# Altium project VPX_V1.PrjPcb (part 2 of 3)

## Sheet 28V to 12V drivers.SchDoc
size 431 x 279 mm; Date: Not shown in title block; ApprovedBy: Not shown in title block; CheckedBy: Not shown in title block; Author: Not shown in title block; CompanyName: Not shown in title block; Engineer: Not shown in title block; Organization: Not shown in title block; Address1: Not shown in title block; Address2: Not shown in title block; Address3: Not shown in title block; Address4: Not shown in title block; DocumentNumber: 2; Revision: Use project parameter SCH_Rev; SheetNumber: 4; SheetTotal: 8; PageSetup: Record=PageOptions¦CenterHorizontal=True¦CenterVertical=True¦PrintScale=1.00¦XCorrection=1.00¦YCorrection=1.00¦PrintKind=0¦BorderSize=5000000¦LeftOffset=0¦BottomOffset=0¦Orientation=2¦PaperLength=1000¦PaperWidth=1000¦Scale=100¦PaperSource=15¦PrintQuality=600¦MediaType=1¦DitherType=10¦PaperKind=Letter¦PrintScaleMode=1
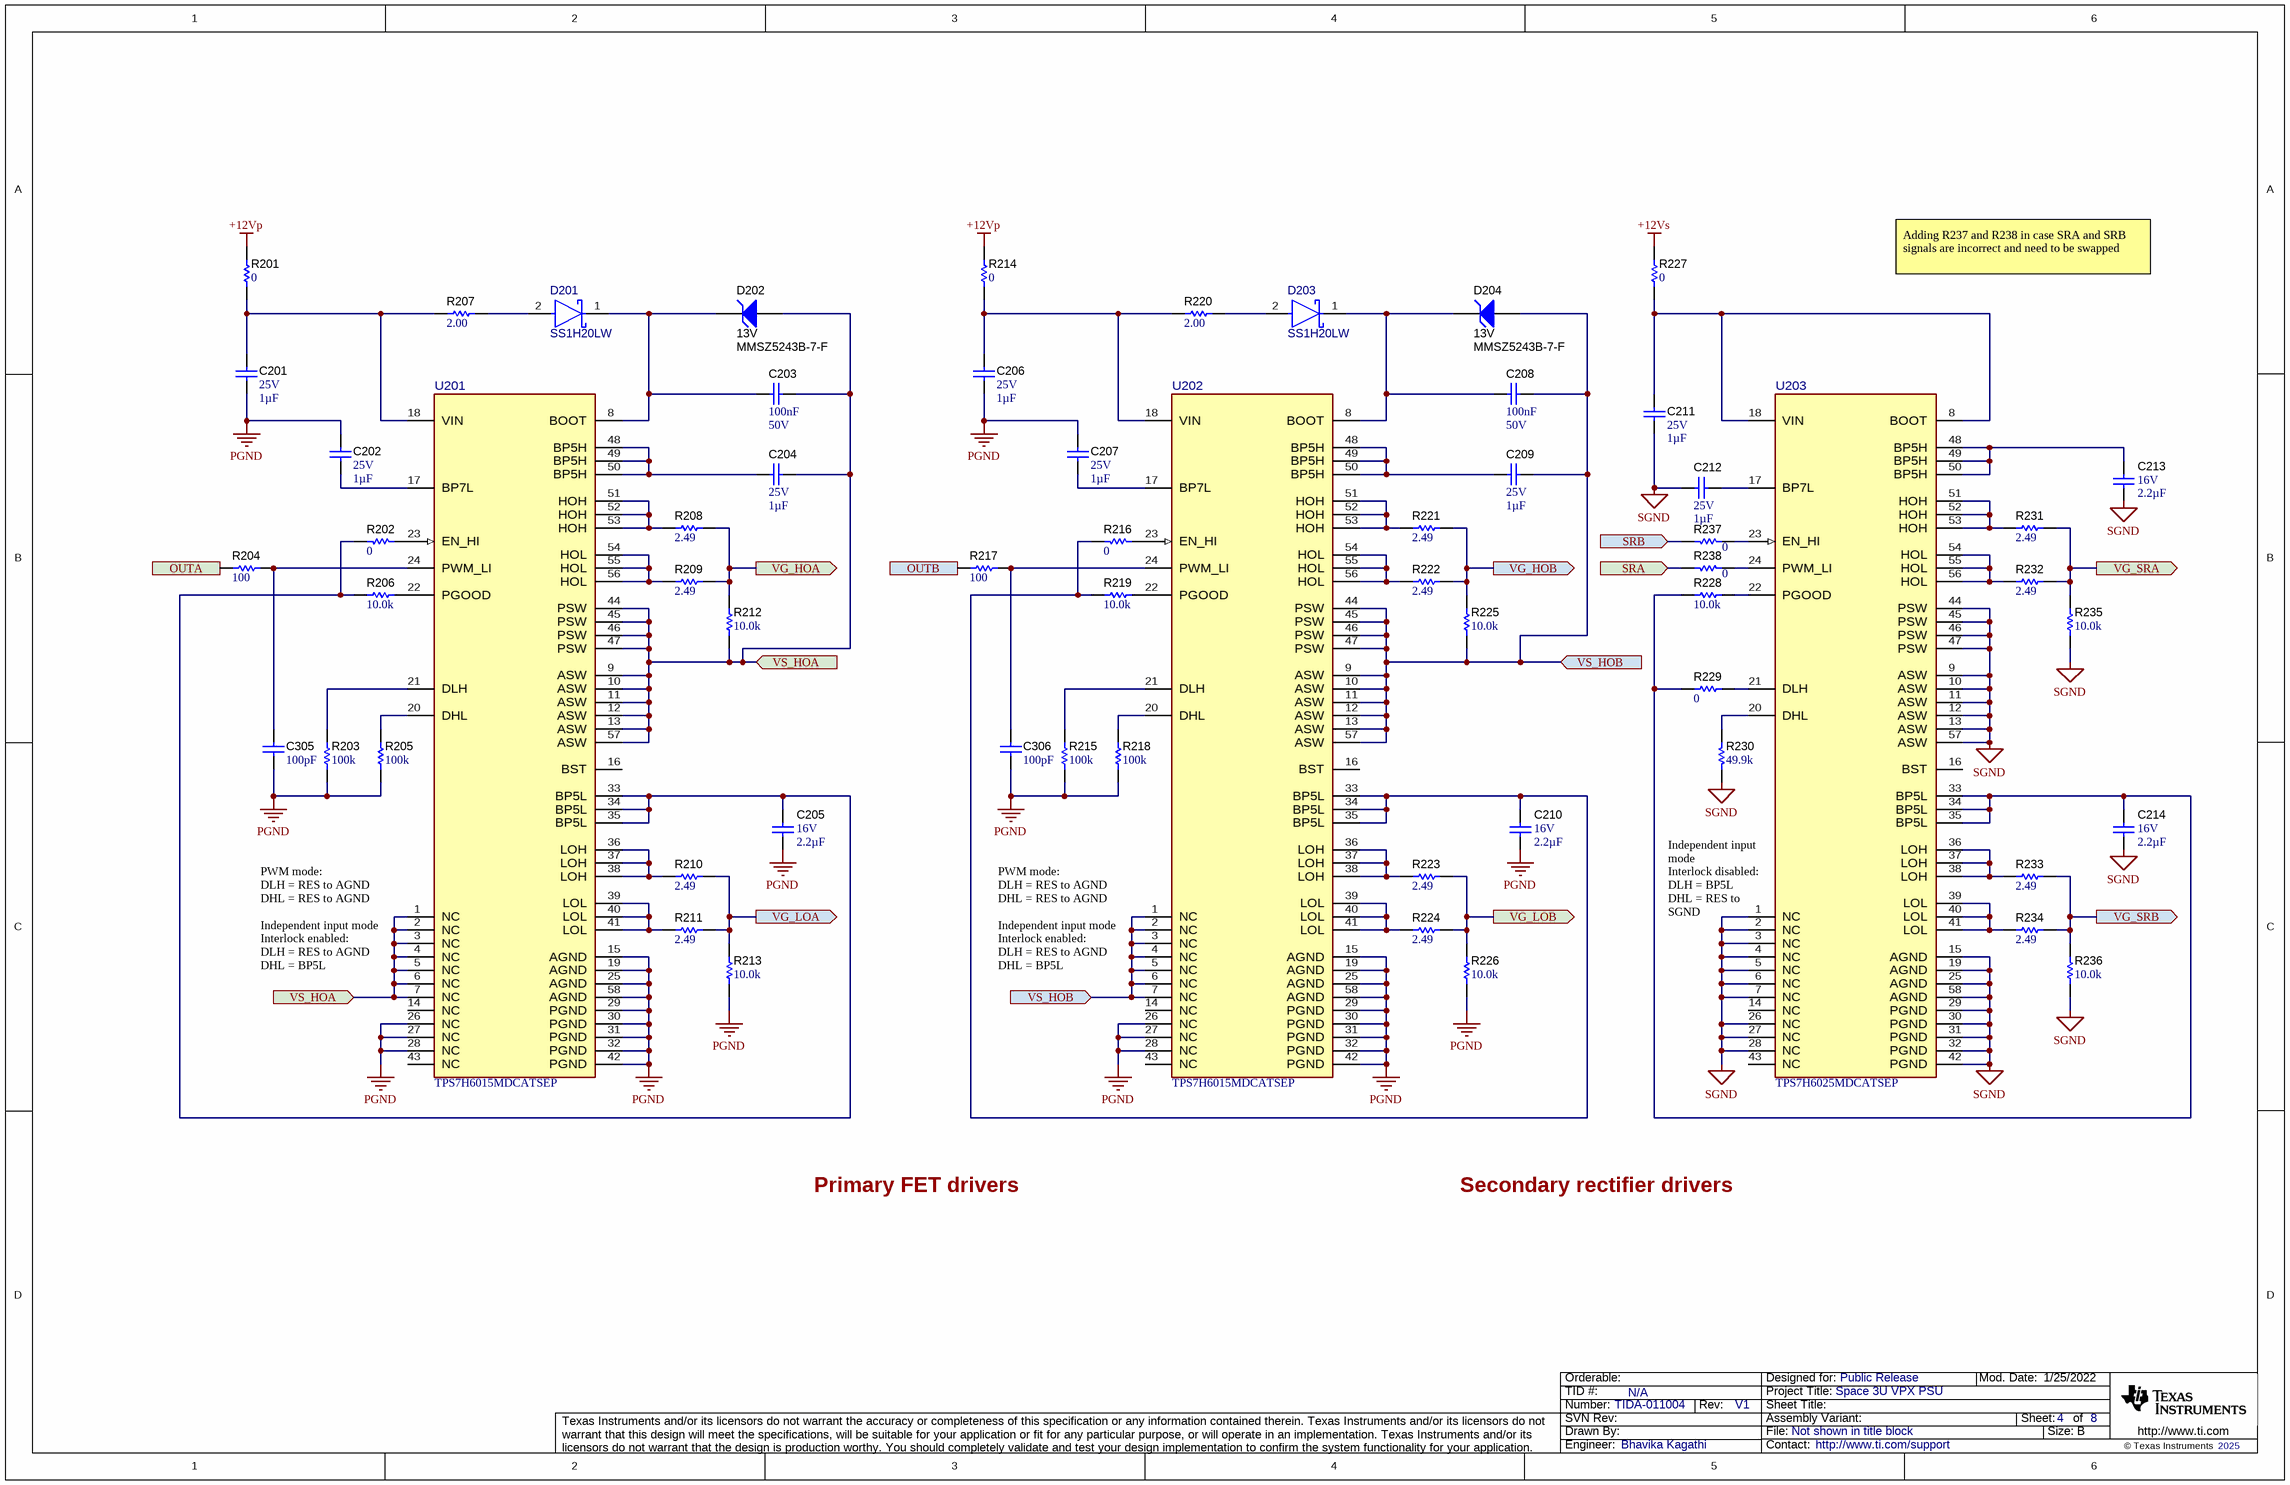
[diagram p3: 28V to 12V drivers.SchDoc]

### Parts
C201  VDC_V: 25V  Cap_F: 1µF  [0603]  (hidden comment: C0603C105K3RACTU)
C202  VDC_V: 25V  Cap_F: 1µF  [0603]  (hidden comment: C0603C105K3RACTU)
C203  Cap_F: 100nF  VDC_V: 50V  [0603_HV]  (hidden comment: C0603C104K5RACAUTO)
C204  VDC_V: 25V  Cap_F: 1µF  [0603]  (hidden comment: C0603C105K3RACTU)
C205  VDC_V: 16V  Cap_F: 2.2µF  [0603_HV]  (hidden comment: GRM188Z71C225KE43)
C206  VDC_V: 25V  Cap_F: 1µF  [0603]  (hidden comment: C0603C105K3RACTU)
C207  VDC_V: 25V  Cap_F: 1µF  [0603]  (hidden comment: C0603C105K3RACTU)
C208  Cap_F: 100nF  VDC_V: 50V  [0603_HV]  (hidden comment: C0603C104K5RACAUTO)
C209  VDC_V: 25V  Cap_F: 1µF  [0603]  (hidden comment: C0603C105K3RACTU)
C210  VDC_V: 16V  Cap_F: 2.2µF  [0603_HV]  (hidden comment: GRM188Z71C225KE43)
C211  VDC_V: 25V  Cap_F: 1µF  [0603]  (hidden comment: C0603C105K3RACTU)
C212  VDC_V: 25V  Cap_F: 1µF  [0603]  (hidden comment: C0603C105K3RACTU)
C213  VDC_V: 16V  Cap_F: 2.2µF  [0603_HV]  (hidden comment: GRM188Z71C225KE43)
C214  VDC_V: 16V  Cap_F: 2.2µF  [0603_HV]  (hidden comment: GRM188Z71C225KE43)
C305  ValueDisplayed: 100pF  [0603_HV]  (hidden comment: GRM1885C1H101JA01D)
C306  ValueDisplayed: 100pF  [0603_HV]  (hidden comment: GRM1885C1H101JA01D)
D201  SS1H20LW  [FP-SS1H20LW_SOD-123W-MFG]
D202  MMSZ5243B-7-F  value 13V  [SOD-123]
D203  SS1H20LW  [FP-SS1H20LW_SOD-123W-MFG]
D204  MMSZ5243B-7-F  value 13V  [SOD-123]
R201  ValueDisplayed: 0  [0603_HV]  (hidden comment: CRCW06030000Z0EA)
R202  ValueDisplayed: 0  [0603_HV]  (hidden comment: CRCW06030000Z0EA)
R203  ValueDisplayed: 100k  [0603_HV]  (hidden comment: CRCW0603100KFKEA)
R204  ValueDisplayed: 100  [0603_HV]  (hidden comment: CRCW0603100RJNEA)
R205  ValueDisplayed: 100k  [0603_HV]  (hidden comment: CRCW0603100KFKEA)
R206  ValueDisplayed: 10.0k  [0603_HV]  (hidden comment: CRCW060310K0FKEA)
R207  ValueDisplayed: 2.00  [0603_HV]  (hidden comment: MCT06030C2008FP500)
R208  ValueDisplayed: 2.49  [0603_HV]  (hidden comment: CRCW06032R49FKEA)
R209  ValueDisplayed: 2.49  [0603_HV]  (hidden comment: CRCW06032R49FKEA)
R210  ValueDisplayed: 2.49  [0603_HV]  (hidden comment: CRCW06032R49FKEA)
R211  ValueDisplayed: 2.49  [0603_HV]  (hidden comment: CRCW06032R49FKEA)
R212  ValueDisplayed: 10.0k  [0603_HV]  (hidden comment: CRCW060310K0FKEA)
R213  ValueDisplayed: 10.0k  [0603_HV]  (hidden comment: CRCW060310K0FKEA)
R214  ValueDisplayed: 0  [0603_HV]  (hidden comment: CRCW06030000Z0EA)
R215  ValueDisplayed: 100k  [0603_HV]  (hidden comment: CRCW0603100KFKEA)
R216  ValueDisplayed: 0  [0603_HV]  (hidden comment: CRCW06030000Z0EA)
R217  ValueDisplayed: 100  [0603_HV]  (hidden comment: CRCW0603100RJNEA)
R218  ValueDisplayed: 100k  [0603_HV]  (hidden comment: CRCW0603100KFKEA)
R219  ValueDisplayed: 10.0k  [0603_HV]  (hidden comment: CRCW060310K0FKEA)
R220  ValueDisplayed: 2.00  [0603_HV]  (hidden comment: MCT06030C2008FP500)
R221  ValueDisplayed: 2.49  [0603_HV]  (hidden comment: CRCW06032R49FKEA)
R222  ValueDisplayed: 2.49  [0603_HV]  (hidden comment: CRCW06032R49FKEA)
R223  ValueDisplayed: 2.49  [0603_HV]  (hidden comment: CRCW06032R49FKEA)
R224  ValueDisplayed: 2.49  [0603_HV]  (hidden comment: CRCW06032R49FKEA)
R225  ValueDisplayed: 10.0k  [0603_HV]  (hidden comment: CRCW060310K0FKEA)
R226  ValueDisplayed: 10.0k  [0603_HV]  (hidden comment: CRCW060310K0FKEA)
R227  ValueDisplayed: 0  [0603_HV]  (hidden comment: CRCW06030000Z0EA)
R228  ValueDisplayed: 10.0k  [0603_HV]  (hidden comment: CRCW060310K0FKEA)
R229  ValueDisplayed: 0  [0603_HV]  (hidden comment: CRCW06030000Z0EA)
R230  ValueDisplayed: 49.9k  [0603_HV]  (hidden comment: CRCW060349K9FKEA)
R231  ValueDisplayed: 2.49  [0603_HV]  (hidden comment: CRCW06032R49FKEA)
R232  ValueDisplayed: 2.49  [0603_HV]  (hidden comment: CRCW06032R49FKEA)
R233  ValueDisplayed: 2.49  [0603_HV]  (hidden comment: CRCW06032R49FKEA)
R234  ValueDisplayed: 2.49  [0603_HV]  (hidden comment: CRCW06032R49FKEA)
R235  ValueDisplayed: 10.0k  [0603_HV]  (hidden comment: CRCW060310K0FKEA)
R236  ValueDisplayed: 10.0k  [0603_HV]  (hidden comment: CRCW060310K0FKEA)
R237  ValueDisplayed: 0  [0603_HV]  (hidden comment: CRCW06030000Z0EA)
R238  ValueDisplayed: 0  [0603_HV]  (hidden comment: CRCW06030000Z0EA)
U201  PartNumber: TPS7H6015MDCATSEP  [DCA0056M-MFG]  (hidden comment: TPS7H6005/EM)
U202  PartNumber: TPS7H6015MDCATSEP  [DCA0056M-MFG]  (hidden comment: TPS7H6005/EM)
U203  PartNumber: TPS7H6025MDCATSEP  [DCA0056M-MFG]  (hidden comment: TPS7H6005/EM)

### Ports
OUTA (in), OUTB (in), SRA (in), SRB (in), VG_HOA (out), VG_HOB (out), VG_LOA (out), VG_LOB (out), VG_SRA (out), VG_SRB (out), VS_HOA (in), VS_HOB (in)

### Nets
+12Vp: R201.1 R214.1
+12Vs: R227.1
PGND: C201.2 C202.1 C205.1 C206.2 C207.1 C210.1 C305.1 C306.1 R203.1 R205.1 R213.2 R215.1 R218.1 R226.2 U201.15(AGND) U201.19(AGND) U201.25(AGND) U201.26(NC) U201.27(NC) U201.28(NC) U201.29(PGND) U201.30(PGND) U201.31(PGND) U201.32(PGND) U201.42(PGND) U201.58(AGND) U202.15(AGND) U202.19(AGND) U202.25(AGND) U202.26(NC) U202.27(NC) U202.28(NC) U202.29(PGND) U202.30(PGND) U202.31(PGND) U202.32(PGND) U202.42(PGND) U202.58(AGND)
SGND: C211.2 C212.1 C213.1 C214.1 R230.2 R235.2 R236.2 U203.1(NC) U203.2(NC) U203.3(NC) U203.4(NC) U203.5(NC) U203.6(NC) U203.7(NC) U203.9(ASW) U203.10(ASW) U203.11(ASW) U203.12(ASW) U203.13(ASW) U203.15(AGND) U203.19(AGND) U203.25(AGND) U203.26(NC) U203.27(NC) U203.28(NC) U203.29(PGND) U203.30(PGND) U203.31(PGND) U203.32(PGND) U203.42(PGND) U203.44(PSW) U203.45(PSW) U203.46(PSW) U203.47(PSW) U203.57(ASW) U203.58(AGND)
OUTA: R204.2 ; port OUTA
OUTB: R217.2 ; port OUTB
SRA: R238.1 ; port SRA
SRB: R237.1 ; port SRB
VG_HOA: R208.1 R209.1 R212.1 ; port VG_HOA
VG_HOB: R221.1 R222.1 R225.1 ; port VG_HOB
VG_LOA: R210.1 R211.1 R213.1 ; port VG_LOA
VG_LOB: R223.1 R224.1 R226.1 ; port VG_LOB
VG_SRA: R231.1 R232.1 R235.1 ; port VG_SRA
VG_SRB: R233.1 R234.1 R236.1 ; port VG_SRB
VS_HOA: C203.2 C204.2 D202.2(A) R212.2 U201.1(NC) U201.2(NC) U201.3(NC) U201.4(NC) U201.5(NC) U201.6(NC) U201.7(NC) U201.9(ASW) U201.10(ASW) U201.11(ASW) U201.12(ASW) U201.13(ASW) U201.44(PSW) U201.45(PSW) U201.46(PSW) U201.47(PSW) U201.57(ASW) ; port VS_HOA
VS_HOB: C208.2 C209.2 D204.2(A) R225.2 U202.1(NC) U202.2(NC) U202.3(NC) U202.4(NC) U202.5(NC) U202.6(NC) U202.7(NC) U202.9(ASW) U202.10(ASW) U202.11(ASW) U202.12(ASW) U202.13(ASW) U202.44(PSW) U202.45(PSW) U202.46(PSW) U202.47(PSW) U202.57(ASW) ; port VS_HOB
NetC201_1: C201.1 R201.2 R207.1 U201.18(VIN)
NetC202_2: C202.2 U201.17(BP7L)
NetC203_1: C203.1 D201.1(CATHODE) D202.1(K) U201.8(BOOT)
NetC204_1: C204.1 U201.48(BP5H) U201.49(BP5H) U201.50(BP5H)
NetC205_2: C205.2 R202.1 R206.2 U201.33(BP5L) U201.34(BP5L) U201.35(BP5L)
NetC206_1: C206.1 R214.2 R220.1 U202.18(VIN)
NetC207_2: C207.2 U202.17(BP7L)
NetC208_1: C208.1 D203.1(CATHODE) D204.1(K) U202.8(BOOT)
NetC209_1: C209.1 U202.48(BP5H) U202.49(BP5H) U202.50(BP5H)
NetC210_2: C210.2 R216.1 R219.2 U202.33(BP5L) U202.34(BP5L) U202.35(BP5L)
NetC211_1: C211.1 R227.2 U203.8(BOOT) U203.18(VIN)
NetC212_2: C212.2 U203.17(BP7L)
NetC213_2: C213.2 U203.48(BP5H) U203.49(BP5H) U203.50(BP5H)
NetC214_2: C214.2 R228.2 R229.1 U203.33(BP5L) U203.34(BP5L) U203.35(BP5L)
NetC305_2: C305.2 R204.1 U201.24(PWM_LI)
NetC306_2: C306.2 R217.1 U202.24(PWM_LI)
NetD201_2: D201.2(ANODE) R207.2
NetD203_2: D203.2(ANODE) R220.2
NetR202_2: R202.2 U201.23(EN_HI)
NetR203_2: R203.2 U201.21(DLH)
NetR205_2: R205.2 U201.20(DHL)
NetR206_1: R206.1 U201.22(PGOOD)
NetR208_2: R208.2 U201.51(HOH) U201.52(HOH) U201.53(HOH)
NetR209_2: R209.2 U201.54(HOL) U201.55(HOL) U201.56(HOL)
NetR210_2: R210.2 U201.36(LOH) U201.37(LOH) U201.38(LOH)
NetR211_2: R211.2 U201.39(LOL) U201.40(LOL) U201.41(LOL)
NetR215_2: R215.2 U202.21(DLH)
NetR216_2: R216.2 U202.23(EN_HI)
NetR218_2: R218.2 U202.20(DHL)
NetR219_1: R219.1 U202.22(PGOOD)
NetR221_2: R221.2 U202.51(HOH) U202.52(HOH) U202.53(HOH)
NetR222_2: R222.2 U202.54(HOL) U202.55(HOL) U202.56(HOL)
NetR223_2: R223.2 U202.36(LOH) U202.37(LOH) U202.38(LOH)
NetR224_2: R224.2 U202.39(LOL) U202.40(LOL) U202.41(LOL)
NetR228_1: R228.1 U203.22(PGOOD)
NetR229_2: R229.2 U203.21(DLH)
NetR230_1: R230.1 U203.20(DHL)
NetR231_2: R231.2 U203.51(HOH) U203.52(HOH) U203.53(HOH)
NetR232_2: R232.2 U203.54(HOL) U203.55(HOL) U203.56(HOL)
NetR233_2: R233.2 U203.36(LOH) U203.37(LOH) U203.38(LOH)
NetR234_2: R234.2 U203.39(LOL) U203.40(LOL) U203.41(LOL)
NetR237_2: R237.2 U203.23(EN_HI)
NetR238_2: R238.2 U203.24(PWM_LI)

Not connected (* = marked no-connect by the designer): U201 14(NC) 16(BST) 43(NC); U202 14(NC) 16(BST) 43(NC); U203 14(NC) 16(BST) 43(NC)

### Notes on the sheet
- Adding R237 and R238 in case SRA and SRB signals are incorrect and need to be swapped
- PWM mode:
  DLH = RES to AGND
  DHL = RES to AGND
- Independent input mode
  Interlock enabled:
  DLH = RES to AGND
  DHL = BP5L
- (near U203) Independent input mode
  Interlock disabled:
  DLH = BP5L
  DHL = RES to SGND
- Primary FET drivers
- Secondary rectifier drivers

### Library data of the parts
C201 C202 C204 C206 C207 C209 C211 C212 = CMP-0006867-4: CAP, CERM, 1 uF, 25 V, +/- 10%, X7R, 0603; Manufacturer: Kemet; AEC Category: Q200; Value: 1uF; SizeX_mm: 1.6; U/M: EA; Value1: Unknown; SizeAreaWB_mm2: 4.68; SizeY_mm: 0.8; TaMin_C: -55°C; SizeZ_mm: 1; Polarized: N; TaMax_C: 125°C; SizeArea_mm2: 1.28
C203 C208 = CMP-0079602-1: CAP, CERM, 0.1 µF, 50 V,+/- 10%, X7R, AEC-Q200 Grade 1, 0603; Manufacturer: Kemet; TaMin_C: -55°C; Polarized: N; SizeAreaWB_mm2: 4.68; U/M: EA; Value: 0.1uF; TaMax_C: 125°C; SizeZ_mm: 1; SizeX_mm: 1.6; SizeY_mm: 0.8; Cap_Case: 0603; SizeArea_mm2: 1.28; AEC Qualified: Y; AEC Category: Q200; ValueDisplayed: 0.1µF
C205 C210 C213 C214 = CMP-0007499-4: CAP, CERM, 2.2 uF, 16 V, +/- 10%, X7R, 0603; Manufacturer: MuRata; TaMin_C: -55°C; Polarized: N; SizeAreaWB_mm2: 4.68; Value1: Unknown; U/M: EA; Value: 2.2uF; TaMax_C: 125°C; SizeZ_mm: 1; SizeX_mm: 1.6; SizeY_mm: 0.8; Cap_Case: 0603; SizeArea_mm2: 1.28; AEC Category: Q200
C305 C306 = CMP-0007171-4: CAP, CERM, 100 pF, 50 V, +/- 5%, C0G/NP0, 0603; Manufacturer: MuRata; TaMin_C: -55°C; Polarized: N; SizeAreaWB_mm2: 4.68; Value1: Unknown; U/M: EA; Value: 100pF; TaMax_C: 125°C; SizeZ_mm: 1; SizeX_mm: 1.6; SizeY_mm: 0.8; Cap_Case: 0603; Value2: 50V; SizeArea_mm2: 1.28; AEC Category: Q200
D201 D203 = CMP-0095320-1: Diode Schottky 200 V 1A Surface Mount SOD-123W; Manufacturer: Taiwan Semiconductor; Max Surge Forward Current: 30A; SizeZ_mm: 1.02mm; AEC Qualified: No; Vf_V: 200V; TJmax_C: 175°C; Peak Reverse Current: 0.1mA; Standoff Height: 0mm
D202 D204 = CMP-0005752-4: Diode, Zener, 13 V, 500 mW, SOD-123; Manufacturer: Diodes Inc.; Value1: 0.5W; SizeAreaWB_mm2: 13.095; RJA_CperW: 350; AEC Category: Q101; SizeZ_mm: 1.35; SizeX_mm: 3.85; Power_W: 500mW; SizeArea_mm2: 6.545; SizeY_mm: 1.7
R201 R202 R214 R216 R227 R229 R237 R238 = CMP-0025697-4: RES, 0, 5%, 0.1 W, AEC-Q200 Grade 0, 0603; Manufacturer: Vishay-Dale; Power_W: 100mW; TempCo: 200 ppm/C; Value_Code: 0000; Value: 0; EIA_Code: E24; SizeX_mm: 1.6; SizeY_mm: 0.8; SizeZ_mm: 1; Value2: 0.1W; SizeArea_mm2: 1.28; AEC Qualified: Y; VDC_V: 75V; AEC Category: Q200
R203 R205 R215 R218 = CMP-0021990-4: RES, 100 k, 1%, 0.1 W, AEC-Q200 Grade 0, 0603; Manufacturer: Vishay-Dale; Power_W: 100mW; TempCo: 100 ppm/C; Value: 100k; EIA_Code: E96; SizeX_mm: 1.6; SizeY_mm: 0.8; SizeZ_mm: 1; Value2: 0.1W; SizeArea_mm2: 1.28; AEC Qualified: Y; VDC_V: 75V; AEC Category: Q200; AEC Grade: 0
R204 R217 = CMP-0025700-4: RES, 100, 5%, 0.1 W, AEC-Q200 Grade 0, 0603; Manufacturer: Vishay-Dale; Power_W: 100mW; TempCo: 200 ppm/C; Value_Code: 100R; Value: 100; EIA_Code: E24; SizeX_mm: 1.6; SizeY_mm: 0.8; SizeZ_mm: 1; Value2: 0.1W; SizeArea_mm2: 1.28; AEC Qualified: Y; VDC_V: 75V; AEC Category: Q200; AEC Grade: 0
R206 R212 R213 R219 R225 R226 R228 R235 R236 = CMP-0021998-4: RES, 10.0 k, 1%, 0.1 W, AEC-Q200 Grade 0, 0603; Manufacturer: Vishay-Dale; Power_W: 100mW; TempCo: 100 ppm/C; Value_Code: 10k0; Value: 10.0k; EIA_Code: E96; Res_ohm: 10k; SizeX_mm: 1.6; SizeY_mm: 0.8; SizeZ_mm: 1; Value2: 0.1W; SizeArea_mm2: 1.28; AEC Qualified: Y; VDC_V: 75V; AEC Category: Q200; AEC Grade: 0
R207 R220 = CMP-0022732-2: RES, 2.00, 1%, 0.125 W, 0603; Manufacturer: Vishay/Beyschlag; Power_W: 125mW; TempCo: 50 ppm/C; Value_Code: 2R00; U/M: EA; Value: 2.00; EIA_Code: E96; Res_ohm: 2; SizeX_mm: 1.6; SizeY_mm: 0.8; Value2: 0.125W; SizeArea_mm2: 1.28; AEC Qualified: N; AEC Category: Q200; SizeZ_mm: 1
R208-R211 R221-R224 R231-R234 = CMP-0022311-4: RES, 2.49, 1%, 0.1 W, AEC-Q200 Grade 0, 0603; Manufacturer: Vishay-Dale; Power_W: 100mW; TempCo: 100 ppm/C; Value_Code: 2R49; Value: 2.49; EIA_Code: E96; SizeX_mm: 1.6; SizeY_mm: 0.8; SizeZ_mm: 1; Value2: 0.1W; SizeArea_mm2: 1.28; AEC Qualified: Y; VDC_V: 75V; AEC Category: Q200; AEC Grade: 0
R230 = CMP-0022447-4: RES, 49.9 k, 1%, 0.1 W, AEC-Q200 Grade 0, 0603; Manufacturer: Vishay-Dale; Power_W: 100mW; TempCo: 100 ppm/C; Value_Code: 49k9; Value: 49.9k; EIA_Code: E96; SizeX_mm: 1.6; SizeY_mm: 0.8; SizeZ_mm: 1; Value2: 0.1W; SizeArea_mm2: 1.28; AEC Qualified: Y; VDC_V: 75V; AEC Category: Q200; AEC Grade: 0
U201-U203 = CMP-0120202-4: Manufacturer: Texas Instruments; SizeZ_mm: 1.2mm; Standoff Height: 0.05mm; AEC Category: Q200; CompType: IC

## Sheet 12V to 5V.SchDoc
size 558 x 431 mm; Date: Not shown in title block; ApprovedBy: Not shown in title block; CheckedBy: Not shown in title block; Author: Not shown in title block; CompanyName: Not shown in title block; Engineer: Not shown in title block; Organization: Not shown in title block; Address1: Not shown in title block; Address2: Not shown in title block; Address3: Not shown in title block; Address4: Not shown in title block; DocumentNumber: 1; Revision: Use project parameter SCH_Rev; SheetNumber: 5; SheetTotal: 8; PageSetup: Record=PageOptions¦CenterHorizontal=True¦CenterVertical=True¦PrintScale=1.00¦XCorrection=1.00¦YCorrection=1.00¦PrintKind=0¦BorderSize=5000000¦LeftOffset=0¦BottomOffset=0¦Orientation=2¦PaperLength=1000¦PaperWidth=1000¦Scale=100¦PaperSource=15¦PrintQuality=600¦MediaType=1¦DitherType=10¦PaperKind=Letter¦PrintScaleMode=1
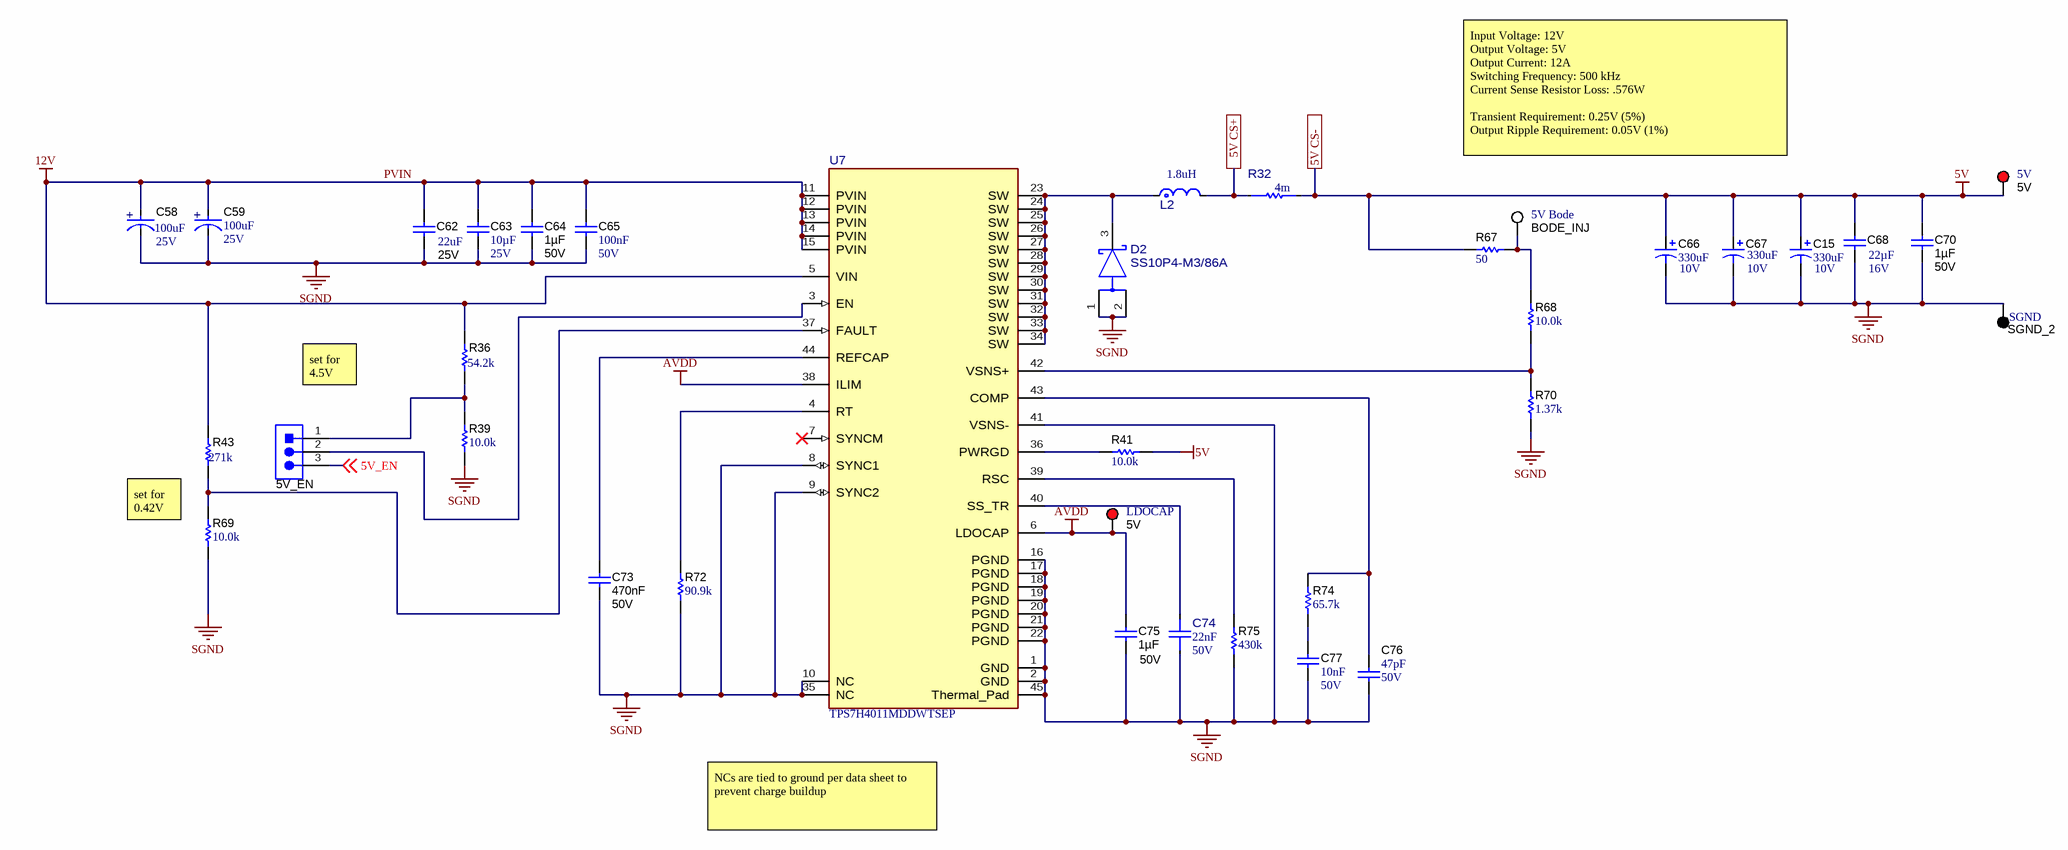
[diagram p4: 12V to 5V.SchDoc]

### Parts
5V  5V  [Keystone5010]
5V_Bode  BODE_INJ  [Keystone5012]
5V_EN  PTT-103-01-L-S  [Samtec_PTT-103-01-x-S]  (value not drawn)
C15  ValueDisplayed: 330uF  VDC_V: 10V  [7343-43]  (hidden comment: T530X337M010ATE006)
C58  ValueDisplayed: 100uF  VDC_V: 25V  [FP-T521D107M025ATE040_2917-MFG]  (hidden comment: T521D107M025ATE040)
C59  ValueDisplayed: 100uF  VDC_V: 25V  [FP-T521D107M025ATE040_2917-MFG]  (hidden comment: T521D107M025ATE040)
C62  Value2: 25V  ValueDisplayed: 22uF  [0805_HV]  (hidden comment: GRM21BR61E226ME44L)
C63  Cap_F: 10µF  VDC_V: 25V  [0805_HV]  (hidden comment: GRM21BZ71E106KE15L)
C64  Cap_F: 1µF  VDC_V: 50V  [0805]  (hidden comment: CL21B105KBFNFNE)
C65  Cap_F: 100nF  VDC_V: 50V  [0805_HV]  (hidden comment: C0805C104K5RACAUTO)
C66  ValueDisplayed: 330uF  VDC_V: 10V  [7343-43]  (hidden comment: T530X337M010ATE006)
C67  ValueDisplayed: 330uF  VDC_V: 10V  [7343-43]  (hidden comment: T530X337M010ATE006)
C68  Value2: 16V  ValueDisplayed: 22µF  [1210_270]  (hidden comment: CL32B226KOJVPNE)
C70  Cap_F: 1µF  VDC_V: 50V  [0805]  (hidden comment: CL21B105KBFNFNE)
C73  Cap_F: 470nF  VDC_V: 50V  [0603]  (hidden comment: C1608X7R1H474K080AC)
C74  Cap_F: 22nF  VDC_V: 50V  [FP-885012206091_0603-MFG]  (hidden comment: 885012206091)
C75  Value2: 50V  Cap_F: 1µF  [0805L]  (hidden comment: CL21B105KBFNFNE)
C76  ValueDisplayed: 47pF  VDC_V: 50V  [0603]  (hidden comment: 06035A470JAT2A)
C77  Cap_F: 10nF  VDC_V: 50V  [0603]  (hidden comment: 885012206089)
D2  SS10P4-M3/86A  [FP-SS10P4-M3_86A_SMPC-MFG]
L2  value 1.8uH  [FP-XGL1060-182MEC_SMT2_10MM0_11MM3-MFG]  (hidden comment: XGL1060-182MEC)
LDOCAP  5V  [Keystone5010]
R32  value 4m  [FP-KRL2012E-M-R004-F-T5_2012-MFG]  (hidden comment: KRL2012E-M-R004-F-T5)
R36  ValueDisplayed: 54.2k  [0603]  (hidden comment: RT0603DRE0754K2L)
R39  ValueDisplayed: 10.0k  [0603]  (hidden comment: RT0603BRD0710KL)
R41  ValueDisplayed: 10.0k  [0603]  (hidden comment: RT0603BRD0710KL)
R43  ValueDisplayed: 271k  [0603]  (hidden comment: RT0603BRD07271KL)
R67  ValueDisplayed: 50  [0603]  (hidden comment: FC0603E50R0BTBST1)
R68  ValueDisplayed: 10.0k  [0603]  (hidden comment: RT0603BRD0710KL)
R69  ValueDisplayed: 10.0k  [0603]  (hidden comment: RT0603BRD0710KL)
R70  ValueDisplayed: 1.37k  [0603]  (hidden comment: RC0603FR-071K37L)
R72  ValueDisplayed: 90.9k  [0603]  (hidden comment: RT0603BRD0790K9L)
R74  ValueDisplayed: 65.7k  [0603]  (hidden comment: RT0603BRD0765K7L)
R75  ValueDisplayed: 430k  [0603]  (hidden comment: CRCW0603430KJNEA)
SGND  SGND_2  [Keystone5011]
U7  TPS7H4011MDDWTSEP  [DDW0044F-MFG]

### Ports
5V CS+, 5V CS-

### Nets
5V: 5V.1 C15.1(+) C66.1(+) C67.1(+) C68.1 C70.1 R32.2 R41.1 R67.1 ; port 5V CS-
AVDD: C75.1 LDOCAP.1 U7.6(LDOCAP) U7.38(ILIM)
PVIN: C58.2(ANODE) C59.2(ANODE) C62.1 C63.1 C64.1 C65.1 R36.2 R43.2 U7.5(VIN) U7.11(PVIN) U7.12(PVIN) U7.13(PVIN) U7.14(PVIN) U7.15(PVIN)  [also labelled 12V]
SGND: C15.2(-) C58.1(CATHODE) C59.1(CATHODE) C62.2 C63.2 C64.2 C65.2 C66.2(-) C67.2(-) C68.2 C70.2 C73.2 C74.1 C75.2 C76.2 C77.2 D2.1(Anode) D2.2(Anode) R39.2 R69.2 R70.1 R72.1 R75.1 SGND.1 U7.1(GND) U7.2(GND) U7.8(SYNC1) U7.9(SYNC2) U7.10(NC) U7.16(PGND) U7.17(PGND) U7.18(PGND) U7.19(PGND) U7.20(PGND) U7.21(PGND) U7.22(PGND) U7.35(NC) U7.41(VSNS-) U7.45(Thermal_Pad)
5V CS+: L2.2 R32.1 ; port 5V CS+
5V_EN: 5V_EN.3 ; off-sheet 5V_EN
Net5V_Bode_1: 5V_Bode.1 R67.2 R68.2
Net5V_EN_1: 5V_EN.1 R36.1 R39.1
Net5V_EN_2: 5V_EN.2 U7.3(EN)
NetC73_1: C73.1 U7.44(REFCAP)
NetC74_2: C74.2 U7.40(SS_TR)
NetC76_1: C76.1 R74.2 U7.43(COMP)
NetC77_1: C77.1 R74.1
NetD2_3: D2.3(Cathode) L2.1 U7.23(SW) U7.24(SW) U7.25(SW) U7.26(SW) U7.27(SW) U7.28(SW) U7.29(SW) U7.30(SW) U7.31(SW) U7.32(SW) U7.33(SW) U7.34(SW)
NetR41_2: R41.2 U7.36(PWRGD)
NetR43_1: R43.1 R69.1 U7.37(FAULT)
NetR68_1: R68.1 R70.2 U7.42(VSNS+)
NetR72_2: R72.2 U7.4(RT)
NetR75_2: R75.2 U7.39(RSC)

Not connected (* = marked no-connect by the designer): U7 7(SYNCM)*

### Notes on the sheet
- Input Voltage: 12V
  Output Voltage: 5V
  Output Current: 12A
  Switching Frequency: 500 kHz
  Current Sense Resistor Loss: .576W
  Transient Requirement: 0.25V (5%)
  Output Ripple Requirement: 0.05V (1%)
- set for 4.5V
- set for 0.42V
- NCs are tied to ground per data sheet to prevent charge buildup

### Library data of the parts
5V LDOCAP = CMP-0055147-2: Test Point, Multipurpose, Red, TH; Manufacturer: Keystone Electronics; CT: TRUE; ContactFinish: Silver; Green_Lifecycle: Active; CNHeader: FALSE; Green_REACh: Passed
5V_Bode = CMP-0055149-2: Test Point, Multipurpose, White, TH; Manufacturer: Keystone Electronics; ContactFinish: Silver; CT: TRUE; CNHeader: FALSE; Green_Lifecycle: Active; Green_REACh: Passed
5V_EN = CMP-0055571-1: Header, 2mm, 3x1, Gold, TH; Manufacturer: Samtec; Current_A: 2.9A; Shrouded: N; CT: FALSE; Cert_UL: Y; Pitch_mm: 2; CNHeader: TRUE; Gender: Male
C15 C66 C67 = CMP-0012657-3: CAP, Tantalum Polymer, 330 uF, 10 V, +/- 20%, 0.006 ohm, 7343-43 SMD; Manufacturer: Kemet; Polarized: Y; CompType: Capacitor; Value: 330uF; Cap_F: 330µF; ESR_ohm: 6m; IRMS_A: 6.7A; TaMin_C: -55°C; TaMax_C: 125°C; AEC Category: Q200; AEC Qualified: N; SizeArea_mm2: 31.39; SizeAreaWB_mm2: 58.59; SizeX_mm: 7.3; SizeY_mm: 4.3
C58 C59 = CMP-0096378-1: Cap Tant Polymer 100uF 25VDC D CASE 20% (7.3 X 4.3 X 2.8mm) SMD 7343-31 0.04 Ohm 105C T/R; Manufacturer: KEMET; Esr: 40m; AEC Qualified: No; Value: 100µF; Leakage Current: 250uA; IRMS_A: 2.81A; Standoff Height: 0mm; Life: 2000Hours; SizeZ_mm: 3.1mm; Dissipation Factor: 10%
C62 = CMP-0008305-2: CAP, CERM, 22 uF, 25 V, +/- 20%, X5R, 0805; Manufacturer: MuRata; TaMin_C: -55°C; Polarized: N; SizeAreaWB_mm2: 6.75; Value1: Unknown; U/M: EA; Value: 22uF; TaMax_C: 85°C; SizeZ_mm: 1.45; SizeX_mm: 2; SizeY_mm: 1.25; Cap_Case: 0805; SizeArea_mm2: 2.5; Cap_F: 22µF; AEC Category: Q200
C63 = CMP-0008378-2: CAP, CERM, 10 uF, 25 V, +/- 10%, X7R, 0805; Manufacturer: MuRata; TaMin_C: -55°C; Polarized: N; SizeAreaWB_mm2: 6.75; Value1: Unknown; U/M: EA; Value: 10uF; TaMax_C: 125°C; SizeZ_mm: 1.45; SizeX_mm: 2; SizeY_mm: 1.25; Cap_Case: 0805; SizeArea_mm2: 2.5; AEC Category: Q200
C64 C70 = CMP-0080611-1: CAP, CERM, 1 µF, 50 V,+/- 10%, X7R, 0805; Manufacturer: Samsung; TaMin_C: -55°C; Polarized: N; SizeAreaWB_mm2: 6.75; U/M: EA; Value: 1uF; TaMax_C: 125°C; SizeZ_mm: 1.45; SizeX_mm: 2; SizeY_mm: 1.25; SizeArea_mm2: 2.5; AEC Category: Q200
C65 = CMP-0007725-2: CAP, CERM, 0.1 uF, 50 V, +/- 10%, X7R, AEC-Q200 Grade 0, 0805; Manufacturer: Kemet; TaMin_C: -55°C; Polarized: N; SizeAreaWB_mm2: 6.75; Value1: Unknown; U/M: EA; Value: 0.1uF; TaMax_C: 125°C; SizeZ_mm: 1.45; SizeX_mm: 2; SizeY_mm: 1.25; Cap_Case: 0805; SizeArea_mm2: 2.5; AEC Qualified: Y; AEC Grade: 0; AEC Category: Q200
C68 = CMP-0083755-1: CAP, CERM, 22 µF, 16 V,+/- 10%, X7R, AEC-Q200 Grade 1, 1210; Manufacturer: Samsung Electro-Mechanics; SizeAreaWB_mm2: 14.7; SizeArea_mm2: 8; AEC Qualified: Y; AEC Category: Q200; Value: 22uF; TaMax_C: 125°C; SizeZ_mm: 2.7; AEC Grade: 1; Polarized: N; TaMin_C: -55°C; SizeY_mm: 2.5; U/M: EA; SizeX_mm: 3.2; Cap_Case: 1210
C73 = CMP-0007050-4: CAP, CERM, 0.47 uF, 50 V, +/- 10%, X7R, 0603; Manufacturer: TDK; TaMin_C: -55°C; ESR_ohm: 10.974m; Polarized: N; SizeAreaWB_mm2: 4.68; Value1: 0.010974 ohm; U/M: EA; Value: 0.47uF; TaMax_C: 125°C; SizeZ_mm: 1; SizeX_mm: 1.6; SizeY_mm: 0.8; SizeArea_mm2: 1.28; IRMS_A: 1.5748A; AEC Category: Q200
C74 = CMP-0120895-1: 0.022 µF ±10% 50V Ceramic Capacitor X7R 0603 (1608 Metric); Manufacturer: Wurth Electronics; AEC Qualified: No; SizeZ_mm: 0.87mm; TempCo: 15%; Value: 22nF
C75 = CMP-0080611-1: CAP, CERM, 1 µF, 50 V,+/- 10%, X7R, 0805; Manufacturer: Samsung; TaMin_C: -55°C; Polarized: N; SizeAreaWB_mm2: 6.75; U/M: EA; Value: 1uF; TaMax_C: 125°C; SizeZ_mm: 1.45; SizeX_mm: 2; SizeY_mm: 1.25; Cap_Case: 0805; SizeArea_mm2: 2.5; AEC Category: Q200
C76 = CMP-0006789-4: CAP, CERM, 47 pF, 50 V, +/- 5%, C0G/NP0, 0603; Manufacturer: AVX; AEC Qualified: N; SizeZ_mm: 1; Value: 47pF; TaMin_C: -55°C; ESR_ohm: 0.174; SizeAreaWB_mm2: 4.68; Value1: 0.174 ohm; U/M: EA; TaMax_C: 125°C; SizeX_mm: 1.6; SizeY_mm: 0.8; SizeArea_mm2: 1.28; AEC Category: Q200
C77 = CMP-0750039-1: CAP, CERM, 0.01 µF, 50 V,+/- 10%, X7R, 0603; Manufacturer: Wurth Elektronik; TaMin_C: -55°C; Polarized: N; SizeAreaWB_mm2: 4.68; U/M: EA; Value: 0.01uF; TaMax_C: 125°C; SizeZ_mm: 1; SizeX_mm: 1.6; SizeY_mm: 0.8; SizeArea_mm2: 1.28; AEC Category: Q200; ValueDisplayed: 0.01µF
D2 = CMP-0120824-2: Diode 40 V 10A Surface Mount TO-277A (SMPC); Manufacturer: Vishay; AEC Category: Q101; AEC Qualified: No; SizeZ_mm: 1.2mm; TJmax_C: 150°C; Vf_V: 40V; Cap_F: 750pF; Max Surge Forward Current: 280A; Peak Reverse Current: 100uA
L2 = CMP-0001536-1: Shielded Power Inductors 1.8uH 28.2A 3.2mOhms AEC-Q200 Grade 1; Manufacturer: Coilcraft; Material: Composite; Isat: 13.5A; DCR_ohm: 3.2m; SizeZ_mm: 6mm; Ind_H: 1.8µH; AEC Qualified: Yes; AEC Grade: Grade 1; Self Resonant Frequency: 28MHz; Shrouded: true; TaMax_C: +125°C; TaMin_C: -40°C; Test Frequency: 1MHz; Tolerance_%: 20%
R32 = CMP-0095678-1: 4 mOhms ±1% 1W Chip Resistor Wide 0805 (2012 Metric), 0508 Automotive AEC-Q200, Current Sense Metal Foil; Manufacturer: Susumu; TempCo: 50ppm/°C; SizeZ_mm: 0.7mm; AEC Qualified: Yes; AEC Grade: Grade 0
R36 = CMP-0025401-2: RES, 54.2 k, 0.5%, 0.1 W, 0603; Manufacturer: Yageo America; Power_W: 100mW; TempCo: 50 ppm/C; Value_Code: 54k2; U/M: EA; Value: 54.2k; EIA_Code: E192; SizeX_mm: 1.6; SizeY_mm: 0.8; SizeZ_mm: 1; Value2: 0.1W; SizeArea_mm2: 1.28; VDC_V: 75V; AEC Category: Q200
R39 R41 R68 R69 = CMP-0023653-3: RES, 10.0 k, 0.1%, 0.1 W, 0603; Manufacturer: Yageo America; Power_W: 100mW; TempCo: 25 ppm/C; Value_Code: 10k0; U/M: EA; Value: 10.0k; EIA_Code: E192; Res_ohm: 10k; SizeX_mm: 1.6; SizeY_mm: 0.8; SizeZ_mm: 1; Value2: 0.1W; SizeArea_mm2: 1.28; VDC_V: 75V; AEC Category: Q200
R43 = CMP-0024020-3: RES, 271 k, 0.1%, 0.1 W, 0603; Manufacturer: Yageo America; Power_W: 100mW; TempCo: 25 ppm/C; U/M: EA; Value: 271k; EIA_Code: E192; SizeX_mm: 1.6; SizeY_mm: 0.8; SizeZ_mm: 1; Value2: 0.1W; SizeArea_mm2: 1.28; VDC_V: 75V; AEC Category: Q200
R67 = CMP-0023387-3: RES, 50, 0.1%, 0.125 W, 0603; Manufacturer: Vishay Thin Film; Power_W: 125mW; TempCo: 25 ppm/C; Value_Code: 50R0; U/M: EA; Value: 50; SizeX_mm: 1.6; SizeY_mm: 0.8; SizeZ_mm: 1; Value2: 0.125W; SizeArea_mm2: 1.28; AEC Qualified: N; VDC_V: 50V; AEC Category: Q200
R70 = CMP-0022876-5: RES, 1.37 k, 1%, 0.1 W, 0603; Manufacturer: Yageo; Power_W: 100mW; TempCo: 100 ppm/C; Value_Code: 1k37; Value: 1.37k; SizeX_mm: 1.6; SizeY_mm: 0.8; SizeZ_mm: 1; Value2: 0.1W; SizeArea_mm2: 1.28; AEC Qualified: N; VDC_V: 75V; AEC Category: Q200; EIA_Code: E96; SizeAreaWB_mm2: 4.68
R72 = CMP-0024528-3: RES, 90.9 k, 0.1%, 0.1 W, 0603; Manufacturer: Yageo America; Power_W: 100mW; TempCo: 25 ppm/C; Value_Code: 90k9; U/M: EA; Value: 90.9k; EIA_Code: E192; SizeX_mm: 1.6; SizeY_mm: 0.8; SizeZ_mm: 1; Value2: 0.1W; SizeArea_mm2: 1.28; VDC_V: 75V; AEC Category: Q200
R74 = CMP-0024410-2: RES, 65.7 k, 0.1%, 0.1 W, 0603; Manufacturer: Yageo America; Power_W: 100mW; TempCo: 25 ppm/C; Value_Code: 65k7; U/M: EA; Value: 65.7k; EIA_Code: E192; SizeX_mm: 1.6; SizeY_mm: 0.8; SizeZ_mm: 1; Value2: 0.1W; SizeArea_mm2: 1.28; AEC Category: Q200; VDC_V: 75V
R75 = CMP-0025808-4: RES, 430 k, 5%, 0.1 W, AEC-Q200 Grade 0, 0603; Manufacturer: Vishay-Dale; Power_W: 100mW; TempCo: 200 ppm/C; Value: 430k; EIA_Code: E24; SizeX_mm: 1.6; SizeY_mm: 0.8; SizeZ_mm: 1; Value2: 0.1W; SizeArea_mm2: 1.28; AEC Qualified: Y; VDC_V: 75V; AEC Category: Q200; AEC Grade: 0
SGND = CMP-0055148-2: Test Point, Multipurpose, Black, TH; Manufacturer: Keystone Electronics; CNHeader: FALSE; ContactFinish: Silver; Green_REACh: Passed; Green_Lifecycle: Active; CT: TRUE
U7 = CMP-0121219-1: 4.5-V to 14-V Input 12-A Radiation Hardened Synchronous Buck Converter; Manufacturer: Texas Instruments; SizeZ_mm: 1.2mm; Max Supply Voltage: 14V; Min Supply Voltage: 4.5V; Nominal Supply Current: 8mA; Number Of Outputs: 1; Output Type: AdjustableProgrammable; Standoff Height: 0.05mm; Switching Frequency: 100-1000kHz; TJmax_C: +125°C; AEC Qualified: No

## Sheet 12 to 3.3V.SchDoc
size 431 x 279 mm; Date: Not shown in title block; ApprovedBy: Not shown in title block; CheckedBy: Not shown in title block; Author: Not shown in title block; CompanyName: Not shown in title block; Engineer: Not shown in title block; Organization: Not shown in title block; Address1: Not shown in title block; Address2: Not shown in title block; Address3: Not shown in title block; Address4: Not shown in title block; DocumentNumber: 2; Revision: Use project parameter SCH_Rev; SheetNumber: 6; SheetTotal: 8; PageSetup: Record=PageOptions¦CenterHorizontal=True¦CenterVertical=True¦PrintScale=1.00¦XCorrection=1.00¦YCorrection=1.00¦PrintKind=0¦BorderSize=5000000¦LeftOffset=0¦BottomOffset=0¦Orientation=2¦PaperLength=1000¦PaperWidth=1000¦Scale=100¦PaperSource=15¦PrintQuality=600¦MediaType=1¦DitherType=10¦PaperKind=Letter¦PrintScaleMode=1
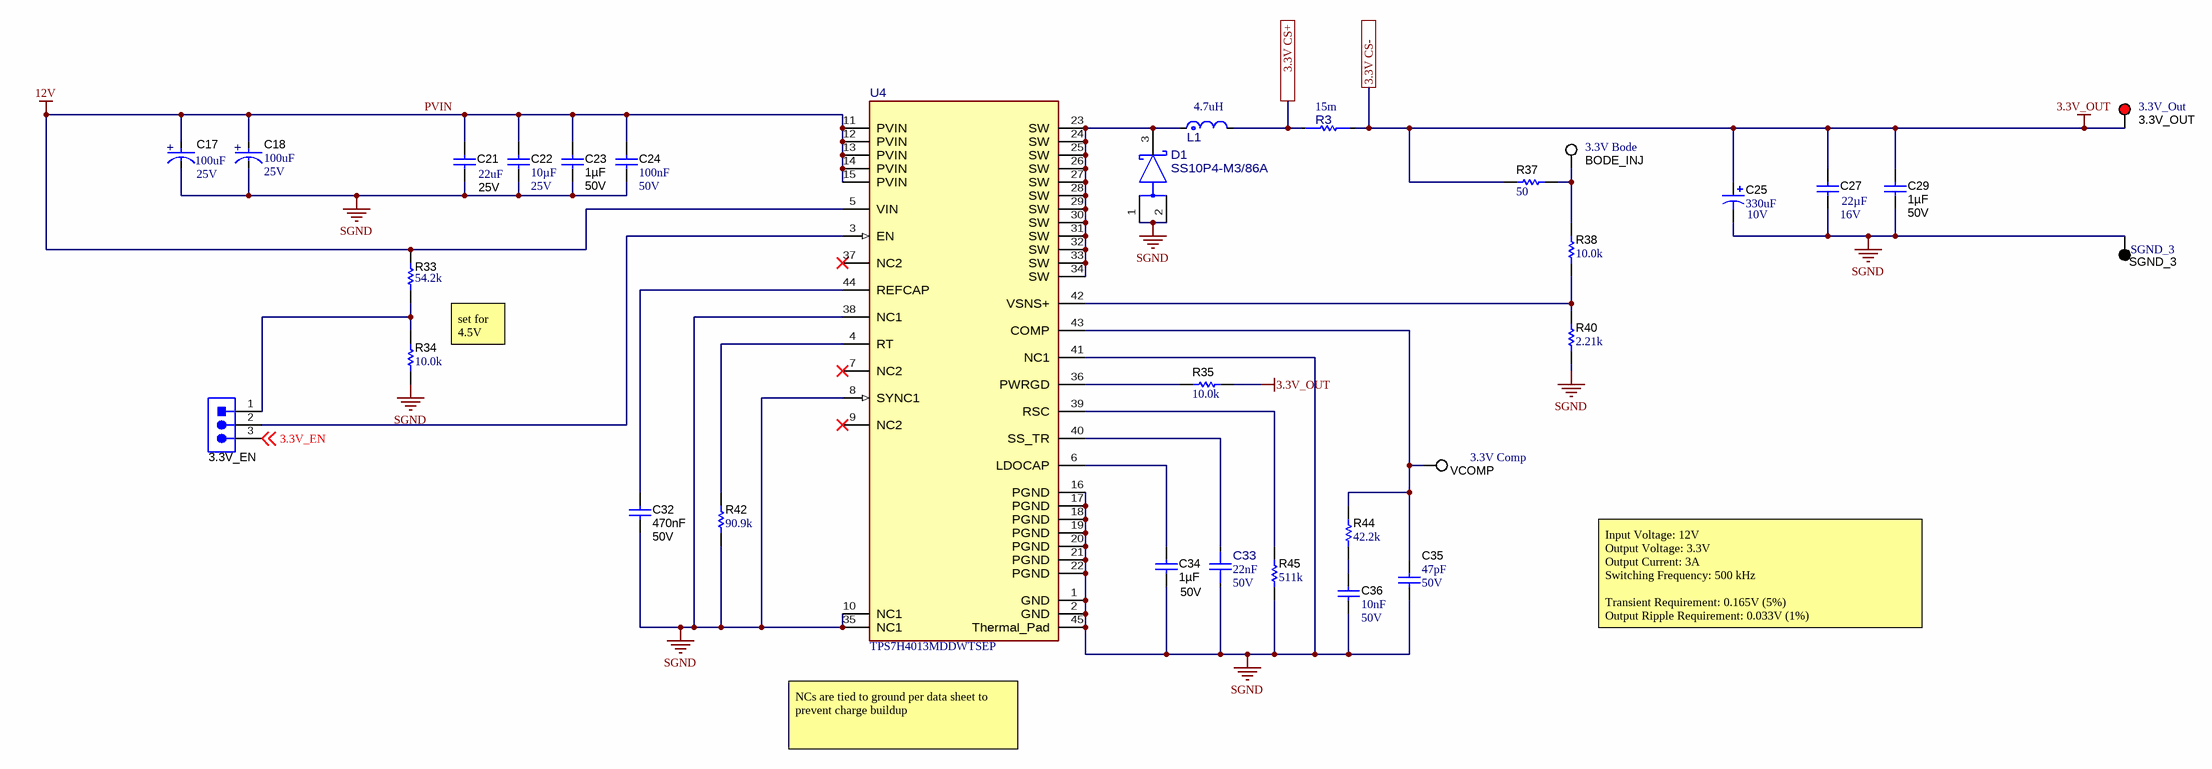
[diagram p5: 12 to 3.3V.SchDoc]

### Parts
3.3V_Bode  BODE_INJ  [Keystone5012]
3.3V_Comp  VCOMP  [Keystone5012]
3.3V_EN  PTT-103-01-L-S  [Samtec_PTT-103-01-x-S]  (value not drawn)
3.3V_Out  3.3V_OUT  [Keystone5010]
C17  ValueDisplayed: 100uF  VDC_V: 25V  [FP-T521D107M025ATE040_2917-MFG]  (hidden comment: T521D107M025ATE040)
C18  ValueDisplayed: 100uF  VDC_V: 25V  [FP-T521D107M025ATE040_2917-MFG]  (hidden comment: T521D107M025ATE040)
C21  Value2: 25V  ValueDisplayed: 22uF  [0805_HV]  (hidden comment: GRM21BR61E226ME44L)
C22  Cap_F: 10µF  VDC_V: 25V  [0805_HV]  (hidden comment: GRM21BZ71E106KE15L)
C23  Cap_F: 1µF  VDC_V: 50V  [0805]  (hidden comment: CL21B105KBFNFNE)
C24  Cap_F: 100nF  VDC_V: 50V  [0805_HV]  (hidden comment: C0805C104K5RACAUTO)
C25  ValueDisplayed: 330uF  Value2: 10V  [7343-43]  (hidden comment: T530X337M010ATE006)
C27  VDC_V: 16V  ValueDisplayed: 22µF  [1210_270]  (hidden comment: CL32B226KOJVPNE)
C29  Cap_F: 1µF  VDC_V: 50V  [0805]  (hidden comment: CL21B105KBFNFNE)
C32  Cap_F: 470nF  VDC_V: 50V  [0603]  (hidden comment: C1608X7R1H474K080AC)
C33  Cap_F: 22nF  VDC_V: 50V  [FP-885012206091_0603-MFG]  (hidden comment: 885012206091)
C34  Value2: 50V  Cap_F: 1µF  [0805L]  (hidden comment: CL21B105KBFNFNE)
C35  ValueDisplayed: 47pF  VDC_V: 50V  [0603]  (hidden comment: 06035A470JAT2A)
C36  Cap_F: 10nF  VDC_V: 50V  [0603]  (hidden comment: 885012206089)
D1  SS10P4-M3/86A  [FP-SS10P4-M3_86A_SMPC-MFG]
L1  value 4.7uH  [FP-XGL1060-472MEC_SMT_IND_10MM0_11MM3-MFG]  (hidden comment: XGL1060-472MEC)
R3  value 15m  [FP-KRL2012E-M-R015-F-T5_0508-MFG]  (hidden comment: KRL2012E-M-R015-F-T5)
R33  ValueDisplayed: 54.2k  [0603]  (hidden comment: RT0603DRE0754K2L)
R34  ValueDisplayed: 10.0k  [0603]  (hidden comment: RT0603BRD0710KL)
R35  ValueDisplayed: 10.0k  [0603]  (hidden comment: RT0603BRD0710KL)
R37  ValueDisplayed: 50  [0603]  (hidden comment: FC0603E50R0BTBST1)
R38  ValueDisplayed: 10.0k  [0603]  (hidden comment: RT0603BRD0710KL)
R40  ValueDisplayed: 2.21k  [0603]  (hidden comment: RC0603FR-072K21L)
R42  ValueDisplayed: 90.9k  [0603]  (hidden comment: RT0603BRD0790K9L)
R44  ValueDisplayed: 42.2k  [0603]  (hidden comment: RT0603BRD0742K2L)
R45  ValueDisplayed: 511k  [0603]  (hidden comment: RT0603BRD07511KL)
SGND_3  SGND_3  [Keystone5011]
U4  TPS7H4013MDDWTSEP  [DDW0044F-MFG]

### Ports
3.3V CS+, 3.3V CS-

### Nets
3.3V_OUT: 3.3V_Out.1 C25.1(+) C27.1 C29.1 R3.2 R35.1 R37.1 ; port 3.3V CS-
PVIN: C17.2(ANODE) C18.2(ANODE) C21.1 C22.1 C23.1 C24.1 R33.2 U4.5(VIN) U4.11(PVIN) U4.12(PVIN) U4.13(PVIN) U4.14(PVIN) U4.15(PVIN)  [also labelled 12V]
SGND: C17.1(CATHODE) C18.1(CATHODE) C21.2 C22.2 C23.2 C24.2 C25.2(-) C27.2 C29.2 C32.2 C33.1 C34.2 C35.2 C36.2 D1.1(Anode) D1.2(Anode) R34.2 R40.1 R42.1 R45.1 SGND_3.1 U4.1(GND) U4.2(GND) U4.8(SYNC1) U4.10(NC1) U4.16(PGND) U4.17(PGND) U4.18(PGND) U4.19(PGND) U4.20(PGND) U4.21(PGND) U4.22(PGND) U4.35(NC1) U4.38(NC1) U4.41(NC1) U4.45(Thermal_Pad)
3.3V CS+: L1.2 R3.1 ; port 3.3V CS+
3.3V_EN: 3.3V_EN.3 ; off-sheet 3.3V_EN
Net3.3V_Bode_1: 3.3V_Bode.1 R37.2 R38.2
Net3.3V_Comp_1: 3.3V_Comp.1 C35.1 R44.2 U4.43(COMP)
Net3.3V_EN_1: 3.3V_EN.1 R33.1 R34.1
Net3.3V_EN_2: 3.3V_EN.2 U4.3(EN)
NetC32_1: C32.1 U4.44(REFCAP)
NetC33_2: C33.2 U4.40(SS_TR)
NetC34_1: C34.1 U4.6(LDOCAP)
NetC36_1: C36.1 R44.1
NetD1_3: D1.3(Cathode) L1.1 U4.23(SW) U4.24(SW) U4.25(SW) U4.26(SW) U4.27(SW) U4.28(SW) U4.29(SW) U4.30(SW) U4.31(SW) U4.32(SW) U4.33(SW) U4.34(SW)
NetR35_2: R35.2 U4.36(PWRGD)
NetR38_1: R38.1 R40.2 U4.42(VSNS+)
NetR42_2: R42.2 U4.4(RT)
NetR45_2: R45.2 U4.39(RSC)

Not connected (* = marked no-connect by the designer): U4 7(NC2)* 9(NC2)* 37(NC2)*

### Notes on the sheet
- set for 4.5V
- Input Voltage: 12V
  Output Voltage: 3.3V
  Output Current: 3A
  Switching Frequency: 500 kHz
  Transient Requirement: 0.165V (5%)
  Output Ripple Requirement: 0.033V (1%)
- NCs are tied to ground per data sheet to prevent charge buildup

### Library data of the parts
3.3V_Bode 3.3V_Comp = CMP-0055149-2: as 5V_Bode on sheet 12V to 5V
3.3V_EN = CMP-0055571-1: as 5V_EN on sheet 12V to 5V
3.3V_Out = CMP-0055147-2: as 5V on sheet 12V to 5V
C17 C18 = CMP-0096378-1: as C58 on sheet 12V to 5V
C21 = CMP-0008305-2: as C62 on sheet 12V to 5V
C22 = CMP-0008378-2: as C63 on sheet 12V to 5V
C23 C29 = CMP-0080611-1: as C64 on sheet 12V to 5V
C24 = CMP-0007725-2: as C65 on sheet 12V to 5V
C25 = CMP-0012657-3: as C15 on sheet 12V to 5V
C27 = CMP-0083755-1: as C68 on sheet 12V to 5V
C32 = CMP-0007050-4: as C73 on sheet 12V to 5V
C33 = CMP-0120895-1: as C74 on sheet 12V to 5V
C34 = CMP-0080611-1: as C75 on sheet 12V to 5V
C35 = CMP-0006789-4: CAP, CERM, 47 pF, 50 V, +/- 5%, C0G/NP0, 0603; Manufacturer: AVX; AEC Qualified: N; SizeZ_mm: 1; Value: 47pF; TaMin_C: -55°C; SizeAreaWB_mm2: 4.68; Value1: 0.174 ohm; U/M: EA; TaMax_C: 125°C; SizeX_mm: 1.6; SizeY_mm: 0.8; SizeArea_mm2: 1.28; AEC Category: Q200; ESR_ohm: 0.174
C36 = CMP-0750039-1: as C77 on sheet 12V to 5V
D1 = CMP-0120824-2: as D2 on sheet 12V to 5V
L1 = CMP-0121657-1: 4.7 µH Shielded Molded Inductor 18.2 A 8.5mOhm Max Nonstandard; Manufacturer: Coilcraft; Material: Composite; Isat: 9.1A; Irms: 18.2A; DCR_ohm: 8.5m; SizeZ_mm: 6mm; Ind_H: 4.7µH; AEC Qualified: Yes; AEC Grade: Grade 1; Self Resonant Frequency: 18MHz; Tolerance_%: 20%; TaMax_C: +125°C; TaMin_C: -40°C; Test Frequency: 1MHz; Shrouded: true
R3 = CMP-0097245-1: 15 mOhms ±1% 1W Chip Resistor Wide 0805 (2012 Metric), 0508 Automotive AEC-Q200, Current Sense Metal Foil; Manufacturer: Susumu; TempCo: 50ppm/°C; SizeZ_mm: 0.7mm; AEC Qualified: Yes; AEC Grade: Grade 0
R33 = CMP-0025401-2: as R36 on sheet 12V to 5V
R34 R35 R38 = CMP-0023653-3: as R39 on sheet 12V to 5V
R37 = CMP-0023387-3: as R67 on sheet 12V to 5V
R40 = CMP-0022984-5: RES, 2.21 k, 1%, 0.1 W, 0603; Manufacturer: Yageo; Power_W: 100mW; TempCo: 100 ppm/C; Value_Code: 2k21; Value: 2.21k; SizeX_mm: 1.6; SizeY_mm: 0.8; SizeZ_mm: 1; Value2: 0.1W; SizeArea_mm2: 1.28; AEC Qualified: N; VDC_V: 75V; AEC Category: Q200; EIA_Code: E96; SizeAreaWB_mm2: 4.68
R42 = CMP-0024528-3: as R72 on sheet 12V to 5V
R44 = CMP-0024230-3: RES, 42.2 k, 0.1%, 0.1 W, 0603; Manufacturer: Yageo America; Power_W: 100mW; TempCo: 25 ppm/C; Value_Code: 42k2; Value: 42.2k; EIA_Code: E192; SizeX_mm: 1.6; SizeY_mm: 0.8; SizeZ_mm: 1; Value2: 0.1W; SizeArea_mm2: 1.28; AEC Category: Q200; VDC_V: 75V; U/M: EA
R45 = CMP-0024309-3: RES, 511 k, 0.1%, 0.1 W, 0603; Manufacturer: Yageo America; Power_W: 100mW; TempCo: 25 ppm/C; U/M: EA; Value: 511k; EIA_Code: E192; SizeX_mm: 1.6; SizeY_mm: 0.8; SizeZ_mm: 1; Value2: 0.1W; SizeArea_mm2: 1.28; VDC_V: 75V; AEC Category: Q200
SGND_3 = CMP-0055148-2: as SGND on sheet 12V to 5V
U4 = CMP-0124169-1: 4.5V to 14V Input, 3A, Radiation Hardened Synchronous Buck Converter; Manufacturer: Texas Instruments; SizeZ_mm: 1.2mm; Nominal Supply Current: 2.6mA; Number Of Outputs: 1; Output Type: AdjustableProgrammable; Standoff Height: 0.05mm; Switching Frequency: 100-1000kHz; TJmax_C: +125°C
